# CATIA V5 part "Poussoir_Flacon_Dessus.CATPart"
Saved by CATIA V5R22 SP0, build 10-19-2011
Part number: Poussoir_Flacon_Dessus
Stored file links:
  C:\Users\La forge\Desktop\CAO_PER_pick&place_2023A\Sous_Ensemble_Flacon\Verin\Poussoir_Flacon\Poussoir_Flacon_Dessus.CATPart

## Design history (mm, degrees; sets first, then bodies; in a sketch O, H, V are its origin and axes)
Body1 (main body)
  Sketch1 on xy-plane, origin (0, 0, 0), H (1, 0, 0), V (0, 1, 0)
    line L1 (90, -20) -> (-90, -20)
    line L2 (-90, -20) -> (-90, 20)
    line L3 (-90, 20) -> (90, 20)
    line L4 (90, 20) -> (90, -20)
    point P5 (80, -10)
    line L5 (70, -10) -> (-70, -10)
    line L6 (-80, 0) -> (-80, 0)
    line L7 (-70, 10) -> (70, 10)
    line L8 (80, 0) -> (80, 0)
    point P6 (-80, -10)
    point P7 (-80, 10)
    point P8 (80, 10)
    arc A1 centre (-70, 0) radius 10 from (-80, 0) to (-70, 10) cw
    arc A2 centre (70, 0) radius 10 from (70, 10) to (80, 0) cw
    arc A3 centre (70, 0) radius 10 from (80, 0) to (70, -10) cw
    arc A4 centre (-70, 0) radius 10 from (-70, -10) to (-80, 0) cw
    length L3 = 180
    length L4 = 40
    distance L4 L8 = 10
    distance L5 L1 = 10
    radius A1 = 10
    radius A2 = 10
    radius A3 = 10
    radius A4 = 10
    horizontal: L1 H, L3 H, L5 H, L7 H
    vertical: L2 V, L4 V, L6 V, L8 V
    equidistance: L4 L2 O, L1 L3 O, P8 P6 O, P5 P7 O
    coincidence: L6 P7, L7 P7, L7 P8, L8 P8, L8 P5, L5 P5, L5 P6, L6 P6
    tangency: A1 L6, A1 L7, A2 L7, A2 L8, A3 L8, A3 L5, A4 L5, A4 L6
  Pad1: profile Sketch1, direction (0, 0, 1), length 5
  Sketch2 on end face of Pad1, origin (0, 0, 5), H (1, 0, 0), V (0, 1, 0)
    line L1 (90, 5) -> (85, 5)
    line L2 (85, 5) -> (85, -5)
    line L3 (85, -5) -> (90, -5)
    line L4 (90, -5) -> (90, 5)
    reference projected line E1 (90, -20) -> (90, 20) from edge [face of Pad1 from Sketch1.L4 | end face of Pad1]
    reference projected line E2 (-90, -20) -> (90, -20) from edge [face of Pad1 from Sketch1.L1 | end face of Pad1]
    length L1 = 5
    distance L3 E2 = 15
    horizontal: L1 H, L3 H
    vertical: L2 V, L4 V
    equidistance: L3 L1 O
    coincidence: L4 E1
  Pocket1: profile Sketch2, direction (0, 0, -1), through (limit type 6)
  Sketch3 on end face of Pad1, origin (0, 0, 5), H (1, 0, 0), V (0, 1, 0)
    point P1 (-7.5, -20)
    line L1 (-7.5, -20) -> (7.5, -20)
    line L2 (7.5, -20) -> (7.5, -15)
    line L3 (7.5, -15) -> (-7.5, -15)
    line L4 (-7.5, -15) -> (-7.5, -20)
    point P2 (7.5, -20)
    point P3 (7.5, -15)
    point P4 (-7.5, -15)
    reference projected line E1 (-90, -20) -> (90, -20) from edge [face of Pad1 from Sketch1.L1 | end face of Pad1]
    point P5 (65, -20)
    line L5 (65, -20) -> (80, -20)
    line L6 (80, -20) -> (80, -15)
    line L7 (80, -15) -> (65, -15)
    line L8 (65, -15) -> (65, -20)
    point P6 (80, -20)
    point P7 (80, -15)
    point P8 (65, -15)
    reference projected line E2 (90, -20) -> (90, 20) from edge [face of Pad1 from Sketch1.L4 | end face of Pad1]
    point P9 (-65, -20)
    point P10 (-80, -20)
    point P11 (-80, -15)
    point P12 (-65, -15)
    line L9 (-65, -20) -> (-80, -20)
    line L10 (-80, -20) -> (-80, -15)
    line L11 (-80, -15) -> (-65, -15)
    line L12 (-65, -15) -> (-65, -20)
    point P13 (-7.5, 20)
    point P14 (7.5, 20)
    point P15 (7.5, 15)
    point P16 (-7.5, 15)
    point P17 (65, 20)
    point P18 (80, 20)
    point P19 (80, 15)
    point P20 (65, 15)
    point P21 (-65, 20)
    point P22 (-80, 20)
    point P23 (-80, 15)
    point P24 (-65, 15)
    line L13 (-7.5, 20) -> (7.5, 20)
    line L14 (7.5, 20) -> (7.5, 15)
    line L15 (7.5, 15) -> (-7.5, 15)
    line L16 (-7.5, 15) -> (-7.5, 20)
    line L17 (65, 20) -> (80, 20)
    line L18 (80, 20) -> (80, 15)
    line L19 (80, 15) -> (65, 15)
    line L20 (65, 15) -> (65, 20)
    line L21 (-65, 20) -> (-80, 20)
    line L22 (-80, 20) -> (-80, 15)
    line L23 (-80, 15) -> (-65, 15)
    line L24 (-65, 15) -> (-65, 20)
    construction line L25 (-18.125, 30) -> (-18.125, -30.0944)
    axis line L26 (18.125, 30) -> (18.125, -30)
    point P29 (36.25, 0)
    point P30 (43.75, -20)
    point P31 (28.75, -20)
    point P32 (28.75, -15)
    point P33 (43.75, -15)
    point P34 (43.75, 20)
    point P35 (28.75, 20)
    point P36 (28.75, 15)
    point P37 (43.75, 15)
    line L27 (43.75, -20) -> (28.75, -20)
    line L28 (28.75, -20) -> (28.75, -15)
    line L29 (28.75, -15) -> (43.75, -15)
    line L30 (43.75, -15) -> (43.75, -20)
    line L31 (43.75, 20) -> (28.75, 20)
    line L32 (28.75, 20) -> (28.75, 15)
    line L33 (28.75, 15) -> (43.75, 15)
    line L34 (43.75, 15) -> (43.75, 20)
    point P38 (-28.75, -20)
    point P39 (-43.75, -20)
    point P40 (-43.75, -15)
    point P41 (-28.75, -15)
    point P42 (-28.75, 20)
    point P43 (-43.75, 20)
    point P44 (-43.75, 15)
    point P45 (-28.75, 15)
    line L35 (-28.75, -20) -> (-43.75, -20)
    line L36 (-43.75, -20) -> (-43.75, -15)
    line L37 (-43.75, -15) -> (-28.75, -15)
    line L38 (-28.75, -15) -> (-28.75, -20)
    line L39 (-28.75, 20) -> (-43.75, 20)
    line L40 (-43.75, 20) -> (-43.75, 15)
    line L41 (-43.75, 15) -> (-28.75, 15)
    line L42 (-28.75, 15) -> (-28.75, 20)
    length L2 = 5
    length L3 = 15
    length L7 = 15
    distance E2 L6 = 10
    distance L25 V = 18.125
    distance V L26 = 18.125
    horizontal: L1 H, L3 H, L5 H, L7 H
    vertical: L2 V, L4 V, L6 V, L8 V, L25 V, L26 V
    coincidence: L1 E1, P5 L1, L7 L3
    equidistance: L4 L2 O
    symmetry: P5 P9 V, P6 P10 V, P7 P11 V, P8 P12 V, L5 L9 V, L6 L10 V, L7 L11 V, L8 L12 V, P1 P13 H, P2 P14 H, P3 P15 H, P4 P16 H, P5 P17 H, P6 P18 H, P7 P19 H, P8 P20 H, P9 P21 H, P10 P22 H, P11 P23 H, P12 P24 H, L1 L13 H, L2 L14 H, L3 L15 H, L4 L16 H, L5 L17 H, L6 L18 H, L7 L19 H, L8 L20 H, L9 L21 H, L10 L22 H, L11 L23 H, L12 L24 H, O P29 L26, P1 P30 L26, P2 P31 L26, P3 P32 L26, P4 P33 L26, P13 P34 L26, P14 P35 L26, P15 P36 L26, P16 P37 L26, L1 L27 L26, L2 L28 L26, L3 L29 L26, L4 L30 L26, L13 L31 L26, L14 L32 L26, L15 L33 L26, L16 L34 L26, P1 P38 L25, P2 P39 L25, P3 P40 L25, P4 P41 L25, P13 P42 L25, P14 P43 L25, P15 P44 L25, P16 P45 L25, L1 L35 L25, L2 L36 L25, L3 L37 L25, L4 L38 L25, L13 L39 L25, L14 L40 L25, L15 L41 L25, L16 L42 L25
  Pocket2: profile Sketch3, direction (0, 0, -1), through (limit type 6)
